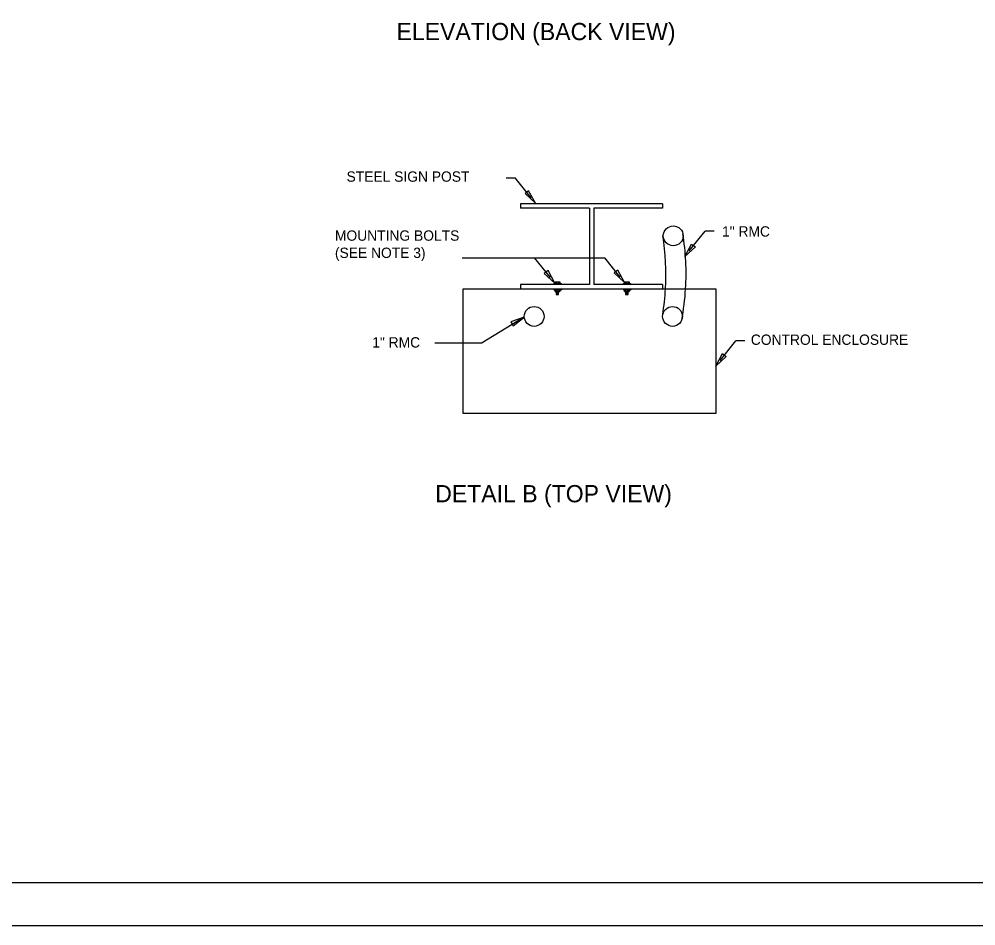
# Model space of a CAD drawing. Extents: x 1299104.6 to 1299141.5, y 239713.3 to 239735.3.
# Drawn here: x 1299118.77 to 1299129.88, y 239713.27 to 239723.8 of the extents above; entities that cross this region are included whole.
import ezdxf

# ---------------------------------------------------------------- set-up
doc = ezdxf.new("R2010")
doc.units = 0
for name, color, linetype in [('DIM TXT', 7, 'Continuous'), ('GS_plotshape_p', 7, 'Continuous'), ('Level 1', 7, 'Continuous'), ('PTEXT', 7, 'Continuous')]:
    doc.layers.add(name, color=color, linetype=linetype)

msp = doc.modelspace()

# ---------------------------------------------------------------- linework, layer by layer
at = {"layer": 'DIM TXT'}
for p, q in [((1299124.428, 239721.959), (1299124.534, 239721.959)), ((1299124.718, 239721.728), (1299124.534, 239721.959)), ((1299126.554, 239721.109), (1299126.738, 239721.34)), ((1299126.843, 239721.34), (1299126.738, 239721.34)), ((1299123.919, 239721.031), (1299125.573, 239721.031)), ((1299124.942, 239720.8), (1299124.758, 239721.031)), ((1299125.752, 239720.806), (1299125.573, 239721.031)), ((1299124.639, 239720.339), (1299124.148, 239720.043)), ((1299123.598, 239720.043), (1299124.148, 239720.043)), ((1299126.912, 239719.836), (1299127.096, 239720.067)), ((1299127.201, 239720.067), (1299127.096, 239720.067))]:
    msp.add_line(p, q, dxfattribs=at)
for points in [[(1299124.689, 239721.809), (1299124.647, 239721.776), (1299124.767, 239721.664)], [(1299126.582, 239721.19), (1299126.625, 239721.157), (1299126.504, 239721.045)], [(1299124.914, 239720.881), (1299124.871, 239720.848), (1299124.992, 239720.736)], [(1299125.724, 239720.887), (1299125.681, 239720.854), (1299125.802, 239720.742)], [(1299124.484, 239720.285), (1299124.51, 239720.238), (1299124.639, 239720.339)], [(1299126.94, 239719.917), (1299126.983, 239719.884), (1299126.863, 239719.772)]]:
    msp.add_lwpolyline(points, close=True, dxfattribs=at)
at = {"layer": 'GS_plotshape_p'}
msp.add_lwpolyline([(1299104.622, 239735.273), (1299138.622, 239735.273), (1299138.622, 239713.273), (1299104.622, 239713.273)], close=True, dxfattribs=at)
at = {"layer": 'Level 1'}
msp.add_lwpolyline([(1299138.122, 239713.773), (1299106.122, 239713.773), (1299106.122, 239734.773), (1299138.122, 239734.773)], close=True, dxfattribs=at)
at = {"layer": 'PTEXT'}
for p, q in [((1299126.245, 239721.658), (1299124.594, 239721.658)), ((1299124.594, 239721.658), (1299124.594, 239721.607)), ((1299125.394, 239721.607), (1299124.594, 239721.607)), ((1299125.394, 239721.607), (1299125.394, 239720.72)), ((1299125.445, 239721.607), (1299125.445, 239720.72)), ((1299126.245, 239721.607), (1299125.445, 239721.607)), ((1299126.245, 239721.658), (1299126.245, 239721.607)), ((1299125.394, 239720.72), (1299124.594, 239720.72)), ((1299124.594, 239720.72), (1299124.594, 239720.67)), ((1299124.982, 239720.72), (1299124.982, 239720.732)), ((1299124.982, 239720.732), (1299125.069, 239720.732)), ((1299124.997, 239720.738), (1299124.997, 239720.75)), ((1299124.997, 239720.75), (1299124.997, 239720.732)), ((1299124.997, 239720.75), (1299125.05, 239720.75)), ((1299125.012, 239720.75), (1299125.012, 239720.732)), ((1299125.033, 239720.75), (1299125.033, 239720.732)), ((1299125.05, 239720.75), (1299125.05, 239720.738)), ((1299125.05, 239720.732), (1299125.05, 239720.75)), ((1299125.069, 239720.72), (1299125.069, 239720.732)), ((1299126.245, 239720.72), (1299125.445, 239720.72)), ((1299125.789, 239720.72), (1299125.789, 239720.733)), ((1299125.789, 239720.733), (1299125.876, 239720.733)), ((1299125.804, 239720.738), (1299125.804, 239720.751)), ((1299125.804, 239720.751), (1299125.804, 239720.733)), ((1299125.804, 239720.751), (1299125.857, 239720.751)), ((1299125.819, 239720.751), (1299125.819, 239720.733)), ((1299125.839, 239720.751), (1299125.839, 239720.733)), ((1299125.857, 239720.751), (1299125.857, 239720.738)), ((1299125.857, 239720.733), (1299125.857, 239720.751)), ((1299125.876, 239720.72), (1299125.876, 239720.733)), ((1299126.245, 239720.72), (1299126.245, 239720.67)), ((1299124.982, 239720.669), (1299124.982, 239720.657)), ((1299124.982, 239720.657), (1299125.069, 239720.657)), ((1299124.997, 239720.639), (1299124.997, 239720.657)), ((1299124.997, 239720.651), (1299124.997, 239720.639)), ((1299124.997, 239720.639), (1299125.05, 239720.639)), ((1299125.008, 239720.639), (1299125.008, 239720.602)), ((1299125.008, 239720.629), (1299125.037, 239720.629)), ((1299125.008, 239720.62), (1299125.037, 239720.62)), ((1299125.008, 239720.611), (1299125.037, 239720.611)), ((1299125.008, 239720.602), (1299125.037, 239720.602)), ((1299125.012, 239720.639), (1299125.012, 239720.657)), ((1299125.033, 239720.639), (1299125.033, 239720.657)), ((1299125.037, 239720.602), (1299125.037, 239720.639)), ((1299125.05, 239720.657), (1299125.05, 239720.639)), ((1299125.05, 239720.639), (1299125.05, 239720.651)), ((1299125.069, 239720.669), (1299125.069, 239720.657)), ((1299125.789, 239720.669), (1299125.789, 239720.657)), ((1299125.789, 239720.657), (1299125.876, 239720.657)), ((1299125.804, 239720.639), (1299125.804, 239720.657)), ((1299125.804, 239720.652), (1299125.804, 239720.639)), ((1299125.804, 239720.639), (1299125.857, 239720.639)), ((1299125.814, 239720.639), (1299125.814, 239720.602)), ((1299125.814, 239720.63), (1299125.844, 239720.63)), ((1299125.814, 239720.621), (1299125.844, 239720.621)), ((1299125.814, 239720.611), (1299125.844, 239720.611)), ((1299125.814, 239720.602), (1299125.844, 239720.602)), ((1299125.819, 239720.639), (1299125.819, 239720.657)), ((1299125.839, 239720.639), (1299125.839, 239720.657)), ((1299125.844, 239720.602), (1299125.844, 239720.639)), ((1299125.857, 239720.657), (1299125.857, 239720.639)), ((1299125.857, 239720.639), (1299125.857, 239720.652)), ((1299125.876, 239720.669), (1299125.876, 239720.657))]:
    msp.add_line(p, q, dxfattribs=at)
msp.add_lwpolyline([(1299126.864, 239720.67), (1299126.864, 239719.223), (1299123.928, 239719.223), (1299123.928, 239720.67)], close=True, dxfattribs=at)
for centre in [(1299126.368, 239721.285), (1299124.753, 239720.349), (1299126.36, 239720.349)]:
    msp.add_circle(centre, 0.115, dxfattribs=at)
for centre, start, end in [((1299123.365, 239720.836), 356.7317, 8.9072), ((1299123.599, 239720.846), 356.5284, 9.136), ((1299123.365, 239720.836), 350.832, 356.7317), ((1299123.599, 239720.846), 349.3496, 356.5284)]:
    msp.add_arc(centre, 2.918, start, end, dxfattribs=at)

# ---------------------------------------------------------------- texts
at = {"layer": 'DIM TXT'}
for s, height, p in [('ELEVATION (BACK VIEW)', 0.2, (1299123.155, 239723.557)), ('STEEL SIGN POST', 0.12, (1299122.575, 239721.913)), ('1" RMC', 0.12, (1299126.935, 239721.276)), ('MOUNTING BOLTS ', 0.12, (1299122.44, 239721.228)), ('(SEE NOTE 3)', 0.12, (1299122.44, 239721.028)), ('CONTROL ENCLOSURE', 0.12, (1299127.269, 239720.019)), ('1" RMC', 0.12, (1299122.873, 239719.988)), ('DETAIL B (TOP VIEW)', 0.2, (1299123.604, 239718.191))]:
    msp.add_text(s, height=height, dxfattribs=at).set_placement(p)

doc.saveas('drawing.dxf')
